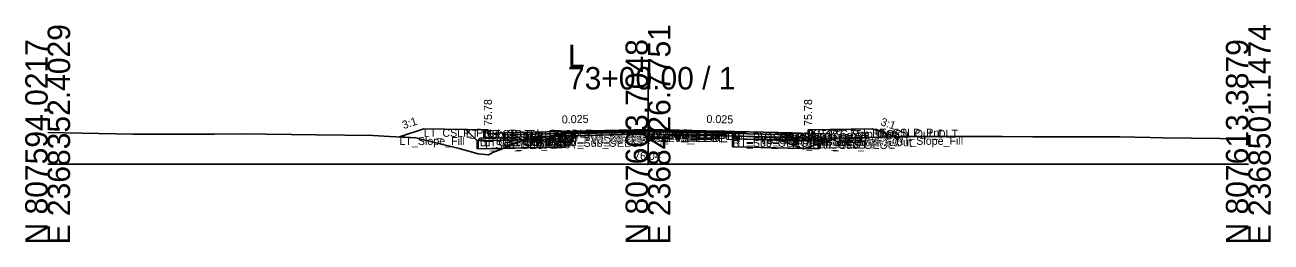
# Model space of a CAD drawing. Extents: x -26 to 8153, y -10 to 9520.
# Drawn here: x 6997.2 to 7152.8, y 3490.3 to 3517.4 of the extents above; entities that cross this region are included whole.
import ezdxf

# ---------------------------------------------------------------- set-up
doc = ezdxf.new("R2010")
doc.units = 0
for name, color, linetype in [('Exist CMT Pavement', 7, 'Continuous'), ('Exist Cross Section Cell', 7, 'Continuous'), ('Exist XS Center Line Elevation Label', 7, 'Continuous'), ('Exist XS Ground Line', 7, 'Continuous'), ('Prop CMT Conc Surface', 7, 'Continuous'), ('Prop CMT Concrete Structures', 7, 'Continuous'), ('Prop CMT Pvmt Course 1', 7, 'Continuous'), ('Prop CMT Pvmt Course 1 CG', 7, 'Continuous'), ('Prop CMT Pvmt Course 1 Wedge', 7, 'Continuous'), ('Prop CMT Pvmt Course 2', 7, 'Continuous'), ('Prop CMT Pvmt Course 2 Wedge', 7, 'Continuous'), ('Prop CMT Pvmt Course 3', 7, 'Continuous'), ('Prop CMT Pvmt Course 3 Wedge', 7, 'Continuous'), ('Prop CMT Pvmt Surface', 7, 'Continuous'), ('Prop CMT Pvmt Wedge Surface 1', 7, 'Continuous'), ('Prop CMT Pvmt Wedge Surface 2', 7, 'Continuous'), ('Prop CMT Pvmt Wedge Surface 3', 7, 'Continuous'), ('Prop CMT Shallow Undercut', 7, 'Continuous'), ('Prop CMT Shallow Undercut Boundary', 7, 'Continuous'), ('Prop CMT Slope Grass', 7, 'Continuous'), ('Prop CMT Subgrade Earthwork', 7, 'Continuous'), ('Prop XS Earthwork Shape', 7, 'Continuous'), ('Prop XS Hydro Elevations', 7, 'Continuous'), ('Prop XS SE Text', 7, 'Continuous'), ('Prop XS Side Slope Text', 7, 'Continuous'), ('Prop XS Subgrade Earthwork', 7, 'Continuous'), ('Scratch_Level_2', 7, 'Continuous'), ('Scratch_Level_6', 7, 'Continuous')]:
    doc.layers.add(name, color=color, linetype=linetype)

msp = doc.modelspace()

# ---------------------------------------------------------------- linework, layer by layer
at = {"layer": 'Exist CMT Pavement'}
for p, q in [((7064.64, 3503.81), (7072.61, 3503.98)), ((7072.61, 3503.98), (7075.03, 3504.04)), ((7075.03, 3504.04), (7083.13, 3503.93)), ((7083.13, 3503.93), (7085.57, 3503.89))]:
    msp.add_line(p, q, dxfattribs=at)
at = {"layer": 'Exist Cross Section Cell'}
for p, q in [((7075, 3500), (7075, 3512.13)), ((7000, 3500), (7075, 3500)), ((7075, 3500), (7150, 3500))]:
    msp.add_line(p, q, dxfattribs=at)
at = {"layer": 'Exist XS Ground Line'}
for p, q in [((7000, 3503.96), (7010.66, 3503.75)), ((7010.66, 3503.75), (7011.5, 3503.75)), ((7011.5, 3503.75), (7012.4, 3503.76)), ((7012.4, 3503.76), (7013.91, 3503.77)), ((7013.91, 3503.77), (7020.78, 3503.77)), ((7020.78, 3503.77), (7024.23, 3503.81)), ((7024.23, 3503.81), (7033.58, 3503.67)), ((7033.58, 3503.67), (7040.63, 3503.58)), ((7040.63, 3503.58), (7042.7, 3503.48)), ((7042.7, 3503.48), (7045.98, 3503.29)), ((7045.98, 3503.29), (7051.42, 3501.95)), ((7055.7, 3501.5), (7059.31, 3502.98)), ((7059.31, 3502.98), (7060.54, 3503.17)), ((7060.54, 3503.17), (7064.64, 3503.81)), ((7064.64, 3503.81), (7072.61, 3503.98)), ((7072.61, 3503.98), (7075.03, 3504.04)), ((7075.03, 3504.04), (7083.13, 3503.93)), ((7083.13, 3503.93), (7085.57, 3503.89)), ((7085.57, 3503.89), (7085.89, 3503.55)), ((7085.89, 3503.55), (7089.5, 3503.4)), ((7089.5, 3503.4), (7090.68, 3503.34)), ((7090.68, 3503.34), (7093.77, 3502.12)), ((7095.06, 3502.13), (7098.46, 3503.26)), ((7098.46, 3503.26), (7102.28, 3503.34)), ((7102.28, 3503.34), (7106.54, 3503.45)), ((7106.54, 3503.45), (7110.17, 3503.45)), ((7110.17, 3503.45), (7119.26, 3503.45)), ((7119.26, 3503.45), (7123.07, 3503.44)), ((7123.07, 3503.44), (7133.92, 3503.44)), ((7133.92, 3503.44), (7137.72, 3503.33)), ((7137.72, 3503.33), (7139.28, 3503.32)), ((7139.28, 3503.32), (7150, 3503.17)), ((7051.42, 3501.95), (7053.77, 3501.3)), ((7053.77, 3501.3), (7055.06, 3501.2)), ((7055.06, 3501.2), (7055.7, 3501.5)), ((7093.77, 3502.12), (7094.43, 3501.91)), ((7094.43, 3501.91), (7095.06, 3502.13))]:
    msp.add_line(p, q, dxfattribs=at)
at = {"layer": 'Prop CMT Conc Surface'}
for points in [[(7055, 3503.78), (7055, 3504.28), (7054.5, 3504.28)], [(7057, 3503.91), (7055, 3503.78)], [(7093, 3503.91), (7095, 3503.78)], [(7095, 3503.78), (7095, 3504.28), (7095.5, 3504.28)]]:
    msp.add_lwpolyline(points, dxfattribs=at)
at = {"layer": 'Prop CMT Concrete Structures'}
for points in [[(7057, 3503.91), (7055, 3503.78), (7055, 3504.28), (7054.5, 3504.28)], [(7054.5, 3504.28), (7054.5, 3503.26), (7057, 3503.32)], [(7057, 3503.32), (7057, 3503.91)], [(7093, 3503.91), (7095, 3503.78), (7095, 3504.28), (7095.5, 3504.28)], [(7095.5, 3504.28), (7095.5, 3503.26), (7093, 3503.32)], [(7093, 3503.32), (7093, 3503.91)]]:
    msp.add_lwpolyline(points, dxfattribs=at)
at = {"layer": 'Prop CMT Pvmt Course 1'}
for points in [[(7075, 3504.36), (7057, 3503.91)], [(7057, 3503.91), (7057, 3503.66)], [(7057, 3503.66), (7064.64, 3503.85)], [(7064.64, 3503.97), (7075, 3504.23)], [(7064.64, 3503.85), (7064.64, 3503.97)], [(7075, 3504.11), (7075, 3504.36)], [(7075, 3504.36), (7093, 3503.91)], [(7075, 3504.11), (7075, 3504.36)], [(7075, 3504.23), (7075, 3504.11), (7075, 3504.11)], [(7085.57, 3503.97), (7075, 3504.23)], [(7075, 3504.23), (7075, 3504.11), (7075, 3504.11)], [(7085.57, 3503.84), (7085.57, 3503.97)], [(7093, 3503.66), (7085.57, 3503.84)], [(7093, 3503.91), (7093, 3503.66)]]:
    msp.add_lwpolyline(points, dxfattribs=at)
at = {"layer": 'Prop CMT Pvmt Course 1 CG'}
for points in [[(7057, 3503.32), (7054, 3503.25), (7053.66, 3502.91)], [(7053.66, 3502.91), (7057, 3502.99)], [(7057, 3502.99), (7057, 3503.32)], [(7093, 3503.32), (7096, 3503.25), (7096.34, 3502.91)], [(7093, 3502.99), (7093, 3503.32)], [(7096.34, 3502.91), (7093, 3502.99)]]:
    msp.add_lwpolyline(points, dxfattribs=at)
at = {"layer": 'Prop CMT Pvmt Course 1 Wedge'}
for points in [[(7075, 3504.23), (7064.64, 3503.97)], [(7075, 3504.23), (7085.57, 3503.97)]]:
    msp.add_lwpolyline(points, dxfattribs=at)
at = {"layer": 'Prop CMT Pvmt Course 2'}
for points in [[(7064.64, 3503.85), (7057, 3503.66)], [(7057, 3503.66), (7057, 3503.33)], [(7057, 3503.33), (7064.64, 3503.52)], [(7064.64, 3503.52), (7064.64, 3503.85)], [(7085.57, 3503.51), (7085.57, 3503.84)], [(7085.57, 3503.84), (7093, 3503.66)], [(7093, 3503.33), (7085.57, 3503.51)], [(7093, 3503.66), (7093, 3503.33)]]:
    msp.add_lwpolyline(points, dxfattribs=at)
at = {"layer": 'Prop CMT Pvmt Course 2 Wedge'}
for points in [[(7075, 3504.11), (7064.64, 3503.85)], [(7075, 3504.11), (7085.57, 3503.84)]]:
    msp.add_lwpolyline(points, dxfattribs=at)
at = {"layer": 'Prop CMT Pvmt Course 3'}
for points in [[(7064.64, 3503.52), (7057, 3503.33)], [(7057, 3503.33), (7057, 3502.99)], [(7057, 3502.99), (7064.64, 3503.18)], [(7064.64, 3503.18), (7064.64, 3503.52)], [(7085.57, 3503.51), (7093, 3503.33)], [(7085.57, 3503.18), (7085.57, 3503.51)], [(7093, 3502.99), (7085.57, 3503.18)], [(7093, 3503.33), (7093, 3502.99)]]:
    msp.add_lwpolyline(points, dxfattribs=at)
at = {"layer": 'Prop CMT Pvmt Course 3 Wedge'}
for points in [[(7075, 3503.78), (7064.64, 3503.52)], [(7075, 3503.78), (7085.57, 3503.51)]]:
    msp.add_lwpolyline(points, dxfattribs=at)
at = {"layer": 'Prop CMT Pvmt Surface'}
for points in [[(7075, 3504.36), (7057, 3503.91)], [(7075, 3504.36), (7093, 3503.91)]]:
    msp.add_lwpolyline(points, dxfattribs=at)
at = {"layer": 'Prop CMT Pvmt Wedge Surface 1'}
for points in [[(7057, 3503.66), (7057, 3503.91)], [(7064.64, 3503.85), (7057, 3503.66)], [(7075, 3504.23), (7064.64, 3503.97)], [(7064.64, 3503.97), (7064.64, 3503.85)], [(7075, 3504.23), (7085.57, 3503.97)], [(7085.57, 3503.97), (7085.57, 3503.84)], [(7085.57, 3503.84), (7093, 3503.66)], [(7093, 3503.66), (7093, 3503.91)]]:
    msp.add_lwpolyline(points, dxfattribs=at)
at = {"layer": 'Prop CMT Pvmt Wedge Surface 2'}
for points in [[(7075, 3504.11), (7057, 3503.66)], [(7057, 3503.66), (7057, 3503.91)], [(7075, 3504.11), (7093, 3503.66)], [(7093, 3503.66), (7093, 3503.91)]]:
    msp.add_lwpolyline(points, dxfattribs=at)
at = {"layer": 'Prop CMT Pvmt Wedge Surface 3'}
for points in [[(7057, 3503.33), (7057, 3503.91)], [(7075, 3503.78), (7057, 3503.33)], [(7075, 3503.78), (7093, 3503.33)], [(7093, 3503.33), (7093, 3503.91)]]:
    msp.add_lwpolyline(points, dxfattribs=at)
at = {"layer": 'Prop CMT Shallow Undercut'}
for points in [[(7059.31, 3502.98), (7059.84, 3503.06), (7064.64, 3503.18), (7064.64, 3502.18), (7056.89, 3501.99)], [(7085.57, 3503.18), (7091.47, 3503.03), (7093.77, 3502.12), (7094.27, 3501.96), (7085.57, 3502.18)], [(7096.34, 3502.56), (7096.34, 3501.91), (7094.56, 3501.95), (7095.06, 3502.13)]]:
    msp.add_lwpolyline(points, close=True, dxfattribs=at)
at = {"layer": 'Prop CMT Shallow Undercut Boundary'}
for p, q in [((7053.66, 3502.91), (7053.66, 3501.91)), ((7064.64, 3503.18), (7064.64, 3502.18)), ((7085.57, 3503.18), (7085.57, 3502.18)), ((7096.34, 3502.91), (7096.34, 3501.91)), ((7053.66, 3501.91), (7064.64, 3502.18)), ((7096.34, 3501.91), (7085.57, 3502.18))]:
    msp.add_line(p, q, dxfattribs=at)
at = {"layer": 'Prop CMT Slope Grass'}
for points in [[(7054.5, 3504.28), (7047, 3504.43), (7043.94, 3503.41)], [(7095.5, 3504.28), (7103, 3504.43), (7105.98, 3503.43)]]:
    msp.add_lwpolyline(points, dxfattribs=at)
at = {"layer": 'Prop CMT Subgrade Earthwork'}
for points in [[(7057, 3502.99), (7053.66, 3502.91), (7052.25, 3504.32)], [(7064.64, 3503.18), (7057, 3502.99)], [(7064.64, 3503.18), (7064.66, 3503.81)], [(7085.57, 3503.18), (7085.56, 3503.89)], [(7085.57, 3503.18), (7093, 3502.99)], [(7093, 3502.99), (7096.34, 3502.91), (7097.75, 3504.32)]]:
    msp.add_lwpolyline(points, dxfattribs=at)
at = {"layer": 'Prop XS Earthwork Shape'}
for points in [[(7053.66, 3501.91), (7056.89, 3501.99), (7055.7, 3501.5), (7055.06, 3501.2), (7053.77, 3501.3), (7051.42, 3501.95), (7045.98, 3503.29), (7043.94, 3503.41), (7047, 3504.43), (7052.25, 3504.32), (7053.66, 3502.91)], [(7102.28, 3503.34), (7105.98, 3503.43), (7103, 3504.43), (7097.75, 3504.32), (7096.34, 3502.91), (7096.34, 3502.56), (7098.46, 3503.26)], [(7053.66, 3501.91), (7056.89, 3501.99), (7059.31, 3502.98), (7059.84, 3503.06), (7057, 3502.99), (7053.66, 3502.91)], [(7064.64, 3503.18), (7059.84, 3503.06), (7059.31, 3502.98), (7056.89, 3501.99), (7064.64, 3502.18)], [(7064.64, 3503.18), (7059.84, 3503.06), (7060.54, 3503.17), (7064.64, 3503.81), (7064.66, 3503.81)], [(7090.68, 3503.34), (7091.47, 3503.03), (7085.57, 3503.18), (7085.56, 3503.89), (7085.57, 3503.89), (7085.89, 3503.55), (7089.5, 3503.4)], [(7093.77, 3502.12), (7094.27, 3501.96), (7085.57, 3502.18), (7085.57, 3503.18), (7091.47, 3503.03)], [(7091.47, 3503.03), (7093, 3502.99), (7096.34, 3502.91), (7096.34, 3502.56), (7095.06, 3502.13), (7094.56, 3501.95), (7094.27, 3501.96), (7093.77, 3502.12)], [(7094.43, 3501.91), (7094.56, 3501.95), (7094.27, 3501.96)], [(7096.34, 3501.91), (7094.56, 3501.95), (7095.06, 3502.13), (7096.34, 3502.56)]]:
    msp.add_lwpolyline(points, close=True, dxfattribs=at)
at = {"layer": 'Prop XS Subgrade Earthwork'}
for p, q in [((7053.66, 3502.91), (7064.64, 3503.18)), ((7085.57, 3503.18), (7096.34, 3502.91))]:
    msp.add_line(p, q, dxfattribs=at)
at = {"layer": 'Scratch_Level_6'}
for points in [[(7059.31, 3502.98), (7059.84, 3503.06), (7064.64, 3503.18), (7064.64, 3502.18), (7056.89, 3501.99)], [(7085.57, 3503.18), (7091.47, 3503.03), (7093.77, 3502.12), (7094.27, 3501.96), (7085.57, 3502.18)], [(7096.34, 3502.56), (7096.34, 3501.91), (7094.56, 3501.95), (7095.06, 3502.13)]]:
    msp.add_lwpolyline(points, close=True, dxfattribs=at)

# ---------------------------------------------------------------- texts
at = {"layer": 'Exist Cross Section Cell'}
for s, p in [('E 2368352.4029', (7002.8, 3490)), ('E 2368426.7751', (7077.8, 3490)), ('E 2368501.1474', (7152.8, 3490)), ('N 807594.0217', (7000, 3490)), ('N 807603.7048', (7075, 3490)), ('N 807613.3879', (7150, 3490))]:
    msp.add_text(s, height=2.8, rotation=90, dxfattribs=at).set_placement(p)
for s, p in [('L', (7065, 3512.13)), ('73+00.00 / 1', (7065, 3509.33))]:
    msp.add_text(s, height=2.8, dxfattribs=at).set_placement(p)
at = {"layer": 'Exist XS Center Line Elevation Label'}
msp.add_text('76.04', height=1, dxfattribs=at).set_placement((7073.26, 3500.54))
at = {"layer": 'Prop XS Hydro Elevations'}
for p in [(7055.5, 3504.78), (7095.5, 3504.78)]:
    msp.add_text('75.78', height=1, rotation=90, dxfattribs=at).set_placement(p)
at = {"layer": 'Prop XS SE Text'}
for rotation, p in [(1.4321, (7064.24, 3505.09)), (358.5679, (7082.29, 3505.17))]:
    msp.add_text('0.025', height=1, rotation=rotation, dxfattribs=at).set_placement(p)
at = {"layer": 'Prop XS Side Slope Text'}
for rotation, p in [(18.4349, (7044.48, 3504.38)), (341.5651, (7103.98, 3504.89))]:
    msp.add_text('3:1', height=1, rotation=rotation, dxfattribs=at).set_placement(p)
at = {"layer": 'Scratch_Level_2'}
for s, p in [('LT_CSLP_Pnt', (7047, 3503.43)), ('RT_CSLP_Pnt', (7103, 3503.43)), ('LT_Slope_Fill', (7043.94, 3502.41)), ('LT_Sub_Trench_Out_DLT', (7052.25, 3503.32)), ('LT_Sub_OEOP', (7053.66, 3501.91)), ('LT_CG1_Shelf_Out', (7054, 3502.25)), ('LT_CG_Top_BOC', (7054.5, 3503.28)), ('LT_CG_Bot_BOC', (7054.5, 3502.26)), ('LT_CG_Top_Face', (7055, 3503.28)), ('LT_CG_Top_Gut', (7055, 3502.78)), ('LT_PV1_OEOT', (7057, 3502.91)), ('LT_PV2_OEOT', (7057, 3502.66)), ('LT_PV3_OEOT', (7057, 3502.33)), ('LT_CG_Bot_IE', (7057, 3502.32)), ('LT_Sub_OEOT', (7057, 3501.99)), ('LT_PV1_OEEOP', (7064.64, 3502.97)), ('LT_PV2_OEEOP', (7064.64, 3502.85)), ('LT_PV_OEEOP_EG', (7064.64, 3502.81)), ('LT_PV3_OEEOP', (7064.64, 3502.52)), ('LT_Sub_OEEOP', (7064.64, 3502.18)), ('LT_PV_Sub_Tie_Out', (7064.66, 3502.81)), ('PV1_PGL', (7075, 3503.36)), ('RT_PV1_IEEOP', (7075, 3503.23)), ('LT_PV1_IEEOP', (7075, 3503.23)), ('RT_PV2_IEEOP', (7075, 3503.11)), ('LT_PV2_IEEOP', (7075, 3503.11)), ('PV2_PGL', (7075, 3503.11)), ('RT_PV_IEEOP_EG', (7075, 3503.04)), ('LT_PV_IEEOP_EG', (7075, 3503.04)), ('RT_PV3_IEEOP', (7075, 3502.78)), ('LT_PV3_IEEOP', (7075, 3502.78)), ('RT_PV_Sub_Tie_Out', (7085.56, 3502.89)), ('RT_PV1_OEEOP', (7085.57, 3502.97)), ('RT_PV_OEEOP_EG', (7085.57, 3502.89)), ('RT_PV2_OEEOP', (7085.57, 3502.84)), ('RT_PV3_OEEOP', (7085.57, 3502.51)), ('RT_Sub_OEEOP', (7085.57, 3502.18)), ('RT_PV1_OEOT', (7093, 3502.91)), ('RT_PV2_OEOT', (7093, 3502.66)), ('RT_PV3_OEOT', (7093, 3502.33)), ('RT_CG_Bot_IE', (7093, 3502.32)), ('RT_Sub_OEOT', (7093, 3501.99)), ('RT_CG_Top_Face', (7095, 3503.28)), ('RT_CG_Top_Gut', (7095, 3502.78)), ('RT_CG_Top_BOC', (7095.5, 3503.28)), ('RT_CG_Bot_BOC', (7095.5, 3502.26)), ('RT_CG1_Shelf_Out', (7096, 3502.25)), ('RT_Sub_OEOP', (7096.34, 3501.91)), ('RT_Sub_Trench_Out_DLT', (7097.75, 3503.32)), ('RT_Slope_Fill', (7105.98, 3502.43))]:
    msp.add_text(s, height=1, dxfattribs=at).set_placement(p)

doc.saveas('drawing.dxf')
